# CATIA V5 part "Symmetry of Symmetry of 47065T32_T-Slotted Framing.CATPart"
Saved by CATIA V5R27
Part number: Symmetry of Symmetry of 47065T32_T-Slotted Framing
Bounding box of the stored display mesh (mm): x -38.1 to 38.1, y -44.45 to 44.45, z -3.175 to 3.175
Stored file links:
  \\triton.meca.polymtl.ca\usagers\zaoue\profiles\Desktop\varm_ass\structure prismatique\Symmetry of Symmetry of 47065T32_T-Slotted Framing.CATPart
  \\triton.meca.polymtl.ca\usagers\zaoue\profiles\Desktop\varm_ass\structure prismatique\Symmetry of 47065T32_T-Slotted Framing.CATPart
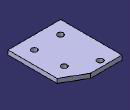
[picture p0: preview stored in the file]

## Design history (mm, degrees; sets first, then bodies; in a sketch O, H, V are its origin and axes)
Body1 (main body)
  Body2 "Corps du corps principal d'origine"
    Solid1: linked copy from another document
  Assemble1: tool Body2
